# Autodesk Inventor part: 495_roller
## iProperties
Author: Administrator
Shininess: 64.0
Angle Display Precision: 2
Document Length Units: 11272
Document Angle Units: 11286
Document Time Units: 11279
Document Mass Units: 11290
Document Length Units Precision: 3
Document Angle Units Precision: 2
Compacted: True
PropertySet Name: _Private Model Information
Created: 2002-03
Part Number: 495_roller
Material: Stainless Steel, 440C
Document SubType Name: Modeling
Designer: Administrator
Control State: 0
Master: False
Checked Out: False
PropertySet Name: Design Tracking Control
Density: 0.0
Volumn: 0.0
Area: 0.0
PropertySet Name: Model Information
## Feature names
1. Revolution1
